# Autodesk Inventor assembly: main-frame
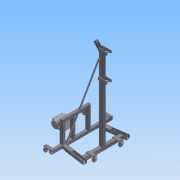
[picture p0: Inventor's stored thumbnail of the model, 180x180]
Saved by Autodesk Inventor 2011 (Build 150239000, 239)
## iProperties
Created: 2020-12
Part Number: main-frame
Document SubType Name: Weldment
Designer: PC
Weld Material: Welded Steel Mild
Description: Main Frame
Author: PC
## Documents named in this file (15)
- C:\Users\PC\Documents\Inventor\workshop-crane-powered-by-drill\main-frame.iam
- C:\Users\PC\Documents\Inventor\workshop-crane-powered-by-drill\1_estructura-principal.iam
- C:\Users\PC\Documents\Inventor\workshop-crane-powered-by-drill\estructura-principal\Design Accelerator\Bolted Connection1.iam
- C:\Users\PC\Documents\Inventor\workshop-crane-powered-by-drill\estructura-principal\Design Accelerator\Bolted Connection2.iam
- C:\Users\PC\Documents\Inventor\workshop-crane-powered-by-drill\estructura-principal\Design Accelerator\Bolted Connection3.iam
- C:\Users\PC\Documents\Inventor\workshop-crane-powered-by-drill\estructura-principal\Design Accelerator\Bolted Connection4.iam
- C:\Users\PC\Documents\Inventor\workshop-crane-powered-by-drill\estructura-principal\Design Accelerator\Bolted Connection5.iam
- C:\Users\PC\Documents\Inventor\workshop-crane-powered-by-drill\estructura-principal\Design Accelerator\Bolted Connection6.iam
- C:\Users\PC\Documents\Inventor\workshop-crane-powered-by-drill\estructura-principal\Design Accelerator\Bolted Connection7.iam
- C:\Users\PC\Documents\Inventor\workshop-crane-powered-by-drill\wheel.ipt
- C:\Users\PC\Documents\Inventor\Content Center Files\R2011\en-US\DIN 555\DIN 555-5 - M14.ipt
- C:\Users\PC\Documents\Inventor\workshop-crane-powered-by-drill\pulley.ipt
- C:\Users\PC\Documents\Inventor\workshop-crane-powered-by-drill\reducer.ipt
- C:\Users\PC\Documents\Inventor\workshop-crane-powered-by-drill\bearing.ipt
- C:\Users\PC\Documents\Inventor\workshop-crane-powered-by-drill\hollow-shaft.ipt
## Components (20 placed, 8 different names)
1. 1_estructura-principal:1 [sub-assembly] — Mate:1, Mate:2, Mate:3, Mate:4, Mate:5, Mate:6, Mate:7, Mate:8, Mate:9, Mate:10, Mate:11, Mate:12, Mate:13, Mate:14, Insert:1, Insert:2, Insert:3, Insert:4, Angle:1, Insert:9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
2. Bolted Connection:1 [sub-assembly] — Mate:1, Mate:2
3. Bolted Connection:2 [sub-assembly] — Mate:3, Mate:4
4. Bolted Connection:3 [sub-assembly] — Mate:5, Mate:6
5. Bolted Connection:4 [sub-assembly] — Mate:7, Mate:8
6. Bolted Connection:5 [sub-assembly] — Mate:9, Mate:10
7. Bolted Connection:6 [sub-assembly] — Mate:11, Mate:12
8. Bolted Connection:7 [sub-assembly] — Mate:13, Mate:14
9. wheel:1 — Insert:3, Angle:1, Angle:2, Angle:3, Angle:4
10. wheel:2 — Insert:2, Angle:3
11. wheel:3 — Insert:4, Angle:2
12. wheel:4 — Insert:1, Angle:4
13. DIN 555 - replaced by DIN EN 24034 M14:1
14. DIN 555 - replaced by DIN EN 24034 M14:2
15. DIN 555 - replaced by DIN EN 24034 M14:3
16. DIN 555 - replaced by DIN EN 24034 M14:4
17. pulley:1 — Insert:9
18. reducer:1 — Mate:15, Flush:1, Flush:2, Mate:16
19. bearing:1 — Mate:16, Angle:5, Flush:3, Insert:10
20. hollow-shaft:1 — Insert:10
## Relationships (30: Mate 16, Insert 6, Angle 5, Flush 3)
- Mate:1: 1_estructura-principal:1 ↔ Bolted Connection:1
- Mate:2: 1_estructura-principal:1 ↔ Bolted Connection:1
- Mate:3: 1_estructura-principal:1 ↔ Bolted Connection:2
- Mate:4: 1_estructura-principal:1 ↔ Bolted Connection:2
- Mate:5: 1_estructura-principal:1 ↔ Bolted Connection:3
- Mate:6: 1_estructura-principal:1 ↔ Bolted Connection:3
- Mate:7: 1_estructura-principal:1 ↔ Bolted Connection:4
- Mate:8: 1_estructura-principal:1 ↔ Bolted Connection:4
- Mate:9: 1_estructura-principal:1 ↔ Bolted Connection:5
- Mate:10: 1_estructura-principal:1 ↔ Bolted Connection:5
- Mate:11: 1_estructura-principal:1 ↔ Bolted Connection:6
- Mate:12: 1_estructura-principal:1 ↔ Bolted Connection:6
- Mate:13: 1_estructura-principal:1 ↔ Bolted Connection:7
- Mate:14: 1_estructura-principal:1 ↔ Bolted Connection:7
- Insert:1: 1_estructura-principal:1 ↔ wheel:4
- Insert:2: 1_estructura-principal:1 ↔ wheel:2
- Insert:3: 1_estructura-principal:1 ↔ wheel:1
- Insert:4: 1_estructura-principal:1 ↔ wheel:3
- Angle:1: 1_estructura-principal:1 ↔ wheel:1
- Angle:2: wheel:1 ↔ wheel:3
- Angle:3: wheel:1 ↔ wheel:2
- Angle:4: wheel:1 ↔ wheel:4
- Insert:9: 1_estructura-principal:1 ↔ pulley:1
- Mate:15: 1_estructura-principal:1 ↔ reducer:1
- Flush:1: 1_estructura-principal:1 ↔ reducer:1
- Flush:2: 1_estructura-principal:1 ↔ reducer:1
- Mate:16: reducer:1 ↔ bearing:1
- Angle:5: 1_estructura-principal:1 ↔ bearing:1
- Flush:3: 1_estructura-principal:1 ↔ bearing:1
- Insert:10: bearing:1 ↔ hollow-shaft:1
